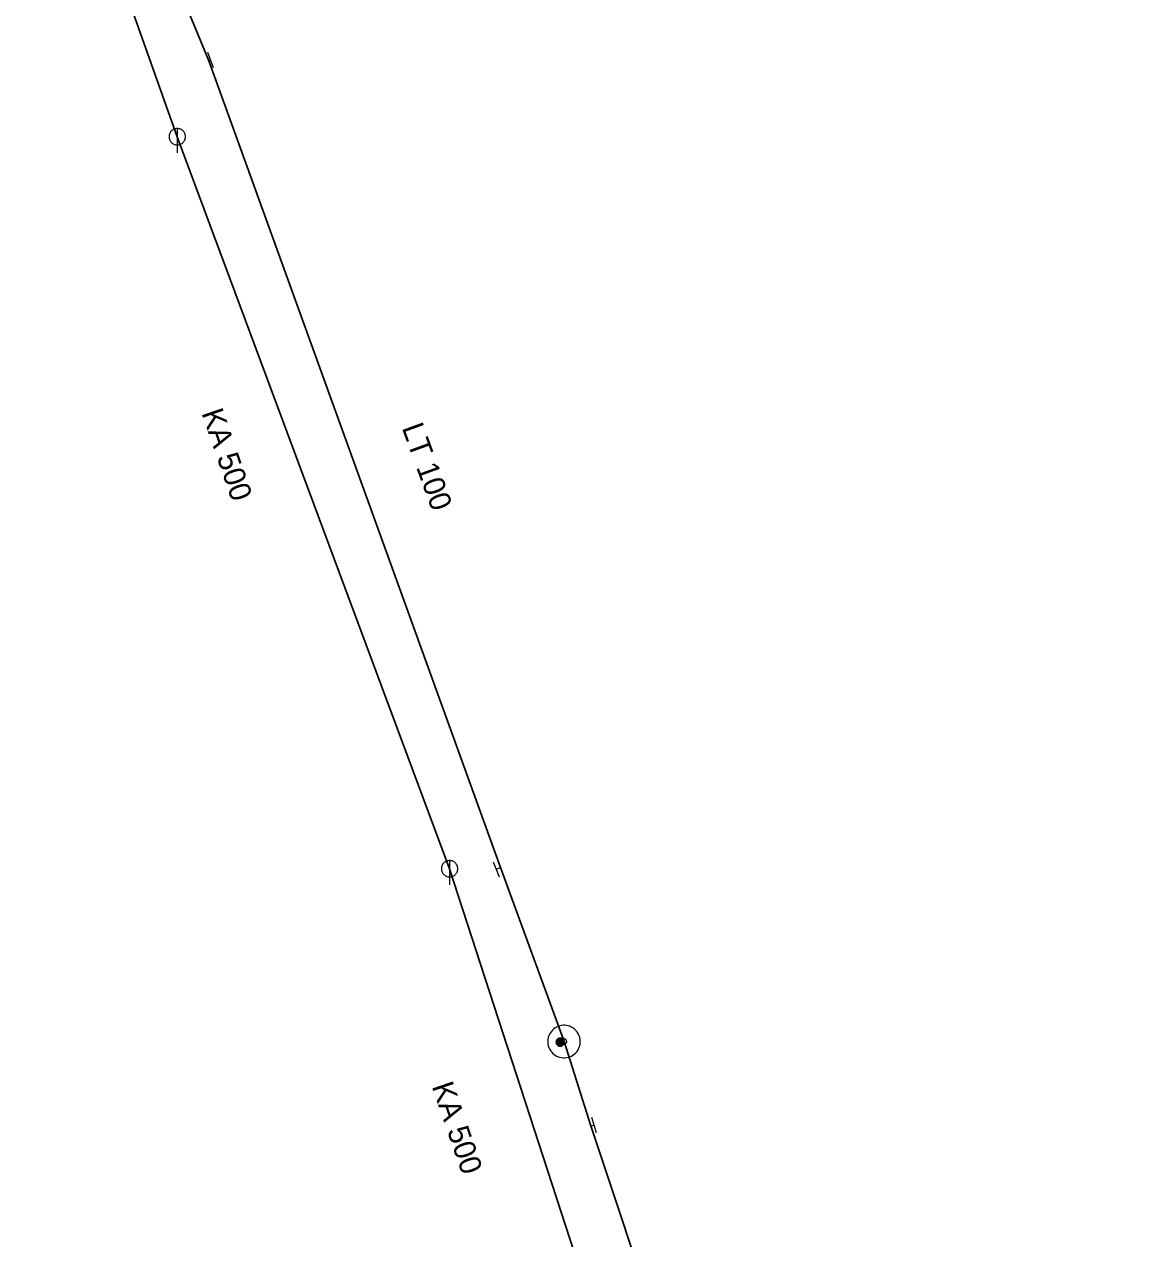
# Model space of a CAD drawing. Extents: x -687515 to -686506, y -974029 to -973461.
# Drawn here: x -687104.06 to -687069.66, y -973628.97 to -973591.65 of the extents above; entities that cross this region are included whole.
import ezdxf
from ezdxf.enums import TextEntityAlignment as Align

# ---------------------------------------------------------------- set-up
doc = ezdxf.new("R2010")
doc.units = 0
doc.header["$LTSCALE"] = 0.27
for name, color, linetype, lineweight in [('1', 7, 'Continuous', 13), ('14', 7, 'Continuous', 25), ('17', 7, 'Continuous', 25), ('22', 7, 'Continuous', 13), ('34', 7, 'Continuous', 13), ('47', 7, 'Continuous', 13), ('9', 7, 'Continuous', 13)]:
    doc.layers.add(name, color=color, linetype=linetype, lineweight=lineweight)

msp = doc.modelspace()

# ---------------------------------------------------------------- linework, layer by layer
at = {"layer": '14'}
for p, q in [((-687099.365, -973595.104), (-687104.065, -973581.877)), ((-687090.996, -973617.6), (-687099.365, -973595.104)), ((-687084.086, -973638.868), (-687090.996, -973617.6))]:
    msp.add_line(p, q, dxfattribs=at)
at = {"layer": '14', "lineweight": 13}
for p, q in [((-687098.39, -973592.77), (-687098.337, -973592.75)), ((-687089.426, -973617.563), (-687089.567, -973617.621)), ((-687087.478, -973622.912), (-687087.599, -973622.929)), ((-687086.649, -973625.5), (-687086.554, -973625.482))]:
    msp.add_line(p, q, dxfattribs=at)
at = {"layer": '17'}
for points in [[(-687087.478, -973622.912), (-687089.426, -973617.563), (-687098.39, -973592.77), (-687099.26, -973590.649), (-687102.57, -973581.78), (-687101.954, -973579.133)], [(-687069.662, -973676.57), (-687086.649, -973625.5), (-687087.478, -973622.912)]]:
    msp.add_lwpolyline(points, dxfattribs=at)
at = {"layer": '22'}
for p, q in [((-687099.364, -973594.852), (-687099.365, -973595.596)), ((-687090.995, -973617.348), (-687090.996, -973618.092))]:
    msp.add_line(p, q, dxfattribs=at)
for points in [[(-687099.113, -973595.104), (-687099.114, -973595.078), (-687099.118, -973595.052), (-687099.124, -973595.026), (-687099.134, -973595.002), (-687099.146, -973594.978), (-687099.16, -973594.956), (-687099.177, -973594.935), (-687099.195, -973594.917), (-687099.216, -973594.9), (-687099.238, -973594.886), (-687099.262, -973594.874), (-687099.286, -973594.864), (-687099.312, -973594.858), (-687099.338, -973594.854), (-687099.364, -973594.852), (-687099.39, -973594.853), (-687099.416, -973594.857), (-687099.442, -973594.863), (-687099.467, -973594.873), (-687099.49, -973594.885), (-687099.512, -973594.899), (-687099.533, -973594.916), (-687099.551, -973594.934), (-687099.568, -973594.955), (-687099.582, -973594.977), (-687099.594, -973595.001), (-687099.604, -973595.025), (-687099.611, -973595.051), (-687099.615, -973595.077), (-687099.617, -973595.103), (-687099.616, -973595.129), (-687099.612, -973595.155), (-687099.605, -973595.181), (-687099.595, -973595.206), (-687099.583, -973595.229), (-687099.569, -973595.251), (-687099.552, -973595.272), (-687099.534, -973595.29), (-687099.513, -973595.307), (-687099.491, -973595.321), (-687099.468, -973595.333), (-687099.443, -973595.343), (-687099.417, -973595.35), (-687099.391, -973595.354), (-687099.365, -973595.356), (-687099.339, -973595.355), (-687099.313, -973595.351), (-687099.287, -973595.344), (-687099.263, -973595.334), (-687099.239, -973595.322), (-687099.217, -973595.308), (-687099.196, -973595.291), (-687099.178, -973595.273), (-687099.161, -973595.252), (-687099.147, -973595.23), (-687099.135, -973595.207), (-687099.125, -973595.182), (-687099.119, -973595.156), (-687099.115, -973595.13)], [(-687090.744, -973617.6), (-687090.745, -973617.574), (-687090.749, -973617.548), (-687090.755, -973617.522), (-687090.765, -973617.498), (-687090.777, -973617.474), (-687090.791, -973617.452), (-687090.808, -973617.431), (-687090.826, -973617.413), (-687090.847, -973617.396), (-687090.869, -973617.382), (-687090.893, -973617.37), (-687090.917, -973617.36), (-687090.943, -973617.354), (-687090.969, -973617.35), (-687090.995, -973617.348), (-687091.021, -973617.349), (-687091.047, -973617.353), (-687091.073, -973617.359), (-687091.098, -973617.369), (-687091.121, -973617.381), (-687091.143, -973617.395), (-687091.164, -973617.412), (-687091.182, -973617.43), (-687091.199, -973617.451), (-687091.213, -973617.473), (-687091.225, -973617.497), (-687091.235, -973617.521), (-687091.242, -973617.547), (-687091.246, -973617.573), (-687091.248, -973617.599), (-687091.247, -973617.625), (-687091.243, -973617.651), (-687091.236, -973617.677), (-687091.226, -973617.702), (-687091.214, -973617.725), (-687091.2, -973617.747), (-687091.183, -973617.768), (-687091.165, -973617.786), (-687091.144, -973617.803), (-687091.122, -973617.817), (-687091.099, -973617.829), (-687091.074, -973617.839), (-687091.048, -973617.846), (-687091.022, -973617.85), (-687090.996, -973617.852), (-687090.97, -973617.851), (-687090.944, -973617.847), (-687090.918, -973617.84), (-687090.894, -973617.83), (-687090.87, -973617.818), (-687090.848, -973617.804), (-687090.827, -973617.787), (-687090.809, -973617.769), (-687090.792, -973617.748), (-687090.778, -973617.726), (-687090.766, -973617.703), (-687090.756, -973617.678), (-687090.75, -973617.652), (-687090.746, -973617.626)]]:
    msp.add_lwpolyline(points, close=True, dxfattribs=at)
at = {"layer": '34'}
for p, q in [((-687098.249, -973592.981), (-687098.424, -973592.518)), ((-687089.66, -973617.391), (-687089.473, -973617.85)), ((-687086.48, -973625.718), (-687086.627, -973625.245))]:
    msp.add_line(p, q, dxfattribs=at)
at = {"layer": '47'}
for points in [[(-687087.297, -973623.378), (-687087.249, -973623.356), (-687087.204, -973623.33), (-687087.162, -973623.299), (-687087.123, -973623.264), (-687087.088, -973623.225), (-687087.057, -973623.182), (-687087.032, -973623.137), (-687087.011, -973623.089), (-687086.995, -973623.04), (-687086.983, -973622.988), (-687086.978, -973622.936), (-687086.979, -973622.883), (-687086.984, -973622.832), (-687086.995, -973622.78), (-687087.011, -973622.731), (-687087.033, -973622.683), (-687087.059, -973622.638), (-687087.091, -973622.595), (-687087.125, -973622.557), (-687087.164, -973622.522), (-687087.207, -973622.491), (-687087.253, -973622.465), (-687087.3, -973622.444), (-687087.35, -973622.428), (-687087.401, -973622.417), (-687087.453, -973622.412), (-687087.506, -973622.412), (-687087.557, -973622.418), (-687087.609, -973622.429), (-687087.658, -973622.445), (-687087.706, -973622.467), (-687087.751, -973622.493), (-687087.794, -973622.524), (-687087.832, -973622.559), (-687087.867, -973622.598), (-687087.898, -973622.64), (-687087.924, -973622.686), (-687087.945, -973622.734), (-687087.961, -973622.784), (-687087.972, -973622.835), (-687087.977, -973622.887), (-687087.977, -973622.939), (-687087.971, -973622.991), (-687087.96, -973623.043), (-687087.944, -973623.092), (-687087.922, -973623.14), (-687087.896, -973623.185), (-687087.866, -973623.227), (-687087.83, -973623.266), (-687087.791, -973623.301), (-687087.749, -973623.332), (-687087.704, -973623.357), (-687087.656, -973623.378), (-687087.606, -973623.394), (-687087.554, -973623.406), (-687087.502, -973623.411), (-687087.45, -973623.41), (-687087.398, -973623.405), (-687087.346, -973623.394)], [(-687087.448, -973622.988), (-687087.439, -973622.985), (-687087.433, -973622.98), (-687087.426, -973622.975), (-687087.42, -973622.97), (-687087.414, -973622.963), (-687087.409, -973622.956), (-687087.404, -973622.949), (-687087.401, -973622.941), (-687087.399, -973622.932), (-687087.396, -973622.924), (-687087.396, -973622.915), (-687087.396, -973622.907), (-687087.397, -973622.898), (-687087.398, -973622.89), (-687087.401, -973622.882), (-687087.404, -973622.873), (-687087.409, -973622.867), (-687087.414, -973622.86), (-687087.419, -973622.854), (-687087.426, -973622.848), (-687087.433, -973622.843), (-687087.44, -973622.838), (-687087.448, -973622.835), (-687087.457, -973622.832), (-687087.465, -973622.83), (-687087.474, -973622.83), (-687087.482, -973622.83), (-687087.491, -973622.831), (-687087.499, -973622.832), (-687087.507, -973622.835), (-687087.516, -973622.838), (-687087.522, -973622.843), (-687087.529, -973622.848), (-687087.535, -973622.853), (-687087.541, -973622.86), (-687087.546, -973622.866), (-687087.551, -973622.874), (-687087.554, -973622.882), (-687087.557, -973622.891), (-687087.559, -973622.899), (-687087.559, -973622.908), (-687087.559, -973622.916), (-687087.558, -973622.925), (-687087.557, -973622.933), (-687087.554, -973622.941), (-687087.551, -973622.95), (-687087.546, -973622.956), (-687087.541, -973622.963), (-687087.536, -973622.969), (-687087.529, -973622.975), (-687087.523, -973622.98), (-687087.515, -973622.985), (-687087.507, -973622.988), (-687087.498, -973622.99), (-687087.49, -973622.993), (-687087.481, -973622.993), (-687087.473, -973622.993), (-687087.464, -973622.992), (-687087.456, -973622.991)]]:
    msp.add_lwpolyline(points, close=True, dxfattribs=at)
at = {"layer": '9'}
for points in [[(-687087.473, -973622.929), (-687087.474, -973622.916), (-687087.476, -973622.903), (-687087.479, -973622.89), (-687087.484, -973622.878), (-687087.49, -973622.866), (-687087.497, -973622.855), (-687087.505, -973622.845), (-687087.515, -973622.835), (-687087.525, -973622.827), (-687087.536, -973622.82), (-687087.548, -973622.814), (-687087.56, -973622.809), (-687087.573, -973622.806), (-687087.586, -973622.804), (-687087.599, -973622.803), (-687087.612, -973622.804), (-687087.625, -973622.806), (-687087.638, -973622.809), (-687087.65, -973622.814), (-687087.662, -973622.82), (-687087.673, -973622.827), (-687087.683, -973622.835), (-687087.693, -973622.845), (-687087.701, -973622.855), (-687087.708, -973622.866), (-687087.714, -973622.878), (-687087.719, -973622.89), (-687087.722, -973622.903), (-687087.724, -973622.916), (-687087.725, -973622.929), (-687087.724, -973622.942), (-687087.722, -973622.955), (-687087.719, -973622.968), (-687087.714, -973622.98), (-687087.708, -973622.992), (-687087.701, -973623.003), (-687087.693, -973623.013), (-687087.683, -973623.023), (-687087.673, -973623.031), (-687087.662, -973623.038), (-687087.65, -973623.044), (-687087.638, -973623.049), (-687087.625, -973623.052), (-687087.612, -973623.054), (-687087.599, -973623.055), (-687087.586, -973623.054), (-687087.573, -973623.052), (-687087.56, -973623.049), (-687087.548, -973623.044), (-687087.536, -973623.038), (-687087.525, -973623.031), (-687087.515, -973623.023), (-687087.505, -973623.013), (-687087.497, -973623.003), (-687087.49, -973622.992), (-687087.484, -973622.98), (-687087.479, -973622.968), (-687087.476, -973622.955), (-687087.474, -973622.942)], [(-687087.493, -973622.929), (-687087.493, -973622.918), (-687087.495, -973622.907), (-687087.498, -973622.896), (-687087.502, -973622.886), (-687087.507, -973622.876), (-687087.513, -973622.867), (-687087.52, -973622.858), (-687087.528, -973622.85), (-687087.537, -973622.843), (-687087.546, -973622.837), (-687087.556, -973622.832), (-687087.566, -973622.828), (-687087.577, -973622.825), (-687087.588, -973622.823), (-687087.599, -973622.823), (-687087.61, -973622.823), (-687087.621, -973622.825), (-687087.632, -973622.828), (-687087.642, -973622.832), (-687087.652, -973622.837), (-687087.661, -973622.843), (-687087.67, -973622.85), (-687087.678, -973622.858), (-687087.685, -973622.867), (-687087.691, -973622.876), (-687087.696, -973622.886), (-687087.7, -973622.896), (-687087.703, -973622.907), (-687087.705, -973622.918), (-687087.705, -973622.929), (-687087.705, -973622.94), (-687087.703, -973622.951), (-687087.7, -973622.962), (-687087.696, -973622.972), (-687087.691, -973622.982), (-687087.685, -973622.991), (-687087.678, -973623), (-687087.67, -973623.008), (-687087.661, -973623.015), (-687087.652, -973623.021), (-687087.642, -973623.026), (-687087.632, -973623.03), (-687087.621, -973623.033), (-687087.61, -973623.035), (-687087.599, -973623.035), (-687087.588, -973623.035), (-687087.577, -973623.033), (-687087.566, -973623.03), (-687087.556, -973623.026), (-687087.546, -973623.021), (-687087.537, -973623.015), (-687087.528, -973623.008), (-687087.52, -973623), (-687087.513, -973622.991), (-687087.507, -973622.982), (-687087.502, -973622.972), (-687087.498, -973622.962), (-687087.495, -973622.951), (-687087.493, -973622.94)], [(-687087.512, -973622.929), (-687087.513, -973622.92), (-687087.514, -973622.911), (-687087.517, -973622.902), (-687087.52, -973622.894), (-687087.524, -973622.886), (-687087.529, -973622.878), (-687087.535, -973622.871), (-687087.541, -973622.865), (-687087.548, -973622.859), (-687087.556, -973622.854), (-687087.564, -973622.85), (-687087.572, -973622.847), (-687087.581, -973622.844), (-687087.59, -973622.843), (-687087.599, -973622.842), (-687087.608, -973622.843), (-687087.617, -973622.844), (-687087.626, -973622.847), (-687087.634, -973622.85), (-687087.642, -973622.854), (-687087.65, -973622.859), (-687087.657, -973622.865), (-687087.663, -973622.871), (-687087.669, -973622.878), (-687087.674, -973622.886), (-687087.678, -973622.894), (-687087.681, -973622.902), (-687087.684, -973622.911), (-687087.685, -973622.92), (-687087.686, -973622.929), (-687087.685, -973622.938), (-687087.684, -973622.947), (-687087.681, -973622.956), (-687087.678, -973622.964), (-687087.674, -973622.972), (-687087.669, -973622.98), (-687087.663, -973622.987), (-687087.657, -973622.993), (-687087.65, -973622.999), (-687087.642, -973623.004), (-687087.634, -973623.008), (-687087.626, -973623.011), (-687087.617, -973623.014), (-687087.608, -973623.015), (-687087.599, -973623.016), (-687087.59, -973623.015), (-687087.581, -973623.014), (-687087.572, -973623.011), (-687087.564, -973623.008), (-687087.556, -973623.004), (-687087.548, -973622.999), (-687087.541, -973622.993), (-687087.535, -973622.987), (-687087.529, -973622.98), (-687087.524, -973622.972), (-687087.52, -973622.964), (-687087.517, -973622.956), (-687087.514, -973622.947), (-687087.513, -973622.938)], [(-687087.532, -973622.929), (-687087.532, -973622.922), (-687087.534, -973622.915), (-687087.535, -973622.908), (-687087.538, -973622.902), (-687087.541, -973622.896), (-687087.545, -973622.89), (-687087.549, -973622.884), (-687087.554, -973622.879), (-687087.56, -973622.875), (-687087.566, -973622.871), (-687087.572, -973622.868), (-687087.578, -973622.865), (-687087.585, -973622.864), (-687087.592, -973622.862), (-687087.599, -973622.862), (-687087.606, -973622.862), (-687087.613, -973622.864), (-687087.62, -973622.865), (-687087.626, -973622.868), (-687087.633, -973622.871), (-687087.638, -973622.875), (-687087.644, -973622.879), (-687087.649, -973622.884), (-687087.653, -973622.89), (-687087.657, -973622.896), (-687087.66, -973622.902), (-687087.663, -973622.908), (-687087.665, -973622.915), (-687087.666, -973622.922), (-687087.666, -973622.929), (-687087.666, -973622.936), (-687087.665, -973622.943), (-687087.663, -973622.95), (-687087.66, -973622.956), (-687087.657, -973622.963), (-687087.653, -973622.968), (-687087.649, -973622.974), (-687087.644, -973622.979), (-687087.638, -973622.983), (-687087.633, -973622.987), (-687087.626, -973622.99), (-687087.62, -973622.993), (-687087.613, -973622.995), (-687087.606, -973622.996), (-687087.599, -973622.996), (-687087.592, -973622.996), (-687087.585, -973622.995), (-687087.578, -973622.993), (-687087.572, -973622.99), (-687087.566, -973622.987), (-687087.56, -973622.983), (-687087.554, -973622.979), (-687087.549, -973622.974), (-687087.545, -973622.968), (-687087.541, -973622.963), (-687087.538, -973622.956), (-687087.535, -973622.95), (-687087.534, -973622.943), (-687087.532, -973622.936)], [(-687087.552, -973622.929), (-687087.552, -973622.924), (-687087.553, -973622.919), (-687087.554, -973622.914), (-687087.556, -973622.91), (-687087.558, -973622.905), (-687087.561, -973622.901), (-687087.564, -973622.898), (-687087.568, -973622.894), (-687087.571, -973622.891), (-687087.575, -973622.888), (-687087.58, -973622.886), (-687087.584, -973622.884), (-687087.589, -973622.883), (-687087.594, -973622.882), (-687087.599, -973622.882), (-687087.604, -973622.882), (-687087.609, -973622.883), (-687087.614, -973622.884), (-687087.618, -973622.886), (-687087.623, -973622.888), (-687087.627, -973622.891), (-687087.631, -973622.894), (-687087.634, -973622.898), (-687087.637, -973622.901), (-687087.64, -973622.905), (-687087.642, -973622.91), (-687087.644, -973622.914), (-687087.645, -973622.919), (-687087.646, -973622.924), (-687087.646, -973622.929), (-687087.646, -973622.934), (-687087.645, -973622.939), (-687087.644, -973622.944), (-687087.642, -973622.948), (-687087.64, -973622.953), (-687087.637, -973622.957), (-687087.634, -973622.961), (-687087.631, -973622.964), (-687087.627, -973622.967), (-687087.623, -973622.97), (-687087.618, -973622.972), (-687087.614, -973622.974), (-687087.609, -973622.975), (-687087.604, -973622.976), (-687087.599, -973622.976), (-687087.594, -973622.976), (-687087.589, -973622.975), (-687087.584, -973622.974), (-687087.58, -973622.972), (-687087.575, -973622.97), (-687087.571, -973622.967), (-687087.568, -973622.964), (-687087.564, -973622.961), (-687087.561, -973622.957), (-687087.558, -973622.953), (-687087.556, -973622.948), (-687087.554, -973622.944), (-687087.553, -973622.939), (-687087.552, -973622.934)], [(-687087.572, -973622.929), (-687087.572, -973622.926), (-687087.572, -973622.923), (-687087.573, -973622.921), (-687087.574, -973622.918), (-687087.575, -973622.915), (-687087.577, -973622.913), (-687087.579, -973622.911), (-687087.581, -973622.909), (-687087.583, -973622.907), (-687087.585, -973622.905), (-687087.588, -973622.904), (-687087.591, -973622.903), (-687087.593, -973622.902), (-687087.596, -973622.902), (-687087.599, -973622.902), (-687087.602, -973622.902), (-687087.605, -973622.902), (-687087.608, -973622.903), (-687087.61, -973622.904), (-687087.613, -973622.905), (-687087.615, -973622.907), (-687087.618, -973622.909), (-687087.62, -973622.911), (-687087.621, -973622.913), (-687087.623, -973622.915), (-687087.624, -973622.918), (-687087.625, -973622.921), (-687087.626, -973622.923), (-687087.626, -973622.926), (-687087.627, -973622.929), (-687087.626, -973622.932), (-687087.626, -973622.935), (-687087.625, -973622.938), (-687087.624, -973622.94), (-687087.623, -973622.943), (-687087.621, -973622.945), (-687087.62, -973622.948), (-687087.618, -973622.95), (-687087.615, -973622.951), (-687087.613, -973622.953), (-687087.61, -973622.954), (-687087.608, -973622.955), (-687087.605, -973622.956), (-687087.602, -973622.956), (-687087.599, -973622.957), (-687087.596, -973622.956), (-687087.593, -973622.956), (-687087.591, -973622.955), (-687087.588, -973622.954), (-687087.585, -973622.953), (-687087.583, -973622.951), (-687087.581, -973622.95), (-687087.579, -973622.948), (-687087.577, -973622.945), (-687087.575, -973622.943), (-687087.574, -973622.94), (-687087.573, -973622.938), (-687087.572, -973622.935), (-687087.572, -973622.932)], [(-687087.591, -973622.929), (-687087.591, -973622.928), (-687087.591, -973622.927), (-687087.592, -973622.927), (-687087.592, -973622.926), (-687087.592, -973622.925), (-687087.593, -973622.924), (-687087.593, -973622.924), (-687087.594, -973622.923), (-687087.594, -973622.923), (-687087.595, -973622.922), (-687087.596, -973622.922), (-687087.597, -973622.922), (-687087.597, -973622.921), (-687087.598, -973622.921), (-687087.599, -973622.921), (-687087.6, -973622.921), (-687087.601, -973622.921), (-687087.601, -973622.922), (-687087.602, -973622.922), (-687087.603, -973622.922), (-687087.604, -973622.923), (-687087.604, -973622.923), (-687087.605, -973622.924), (-687087.605, -973622.924), (-687087.606, -973622.925), (-687087.606, -973622.926), (-687087.607, -973622.927), (-687087.607, -973622.927), (-687087.607, -973622.928), (-687087.607, -973622.929), (-687087.607, -973622.93), (-687087.607, -973622.931), (-687087.607, -973622.931), (-687087.606, -973622.932), (-687087.606, -973622.933), (-687087.605, -973622.934), (-687087.605, -973622.934), (-687087.604, -973622.935), (-687087.604, -973622.935), (-687087.603, -973622.936), (-687087.602, -973622.936), (-687087.601, -973622.937), (-687087.601, -973622.937), (-687087.6, -973622.937), (-687087.599, -973622.937), (-687087.598, -973622.937), (-687087.597, -973622.937), (-687087.597, -973622.937), (-687087.596, -973622.936), (-687087.595, -973622.936), (-687087.594, -973622.935), (-687087.594, -973622.935), (-687087.593, -973622.934), (-687087.593, -973622.934), (-687087.592, -973622.933), (-687087.592, -973622.932), (-687087.592, -973622.931), (-687087.591, -973622.931), (-687087.591, -973622.93)]]:
    msp.add_lwpolyline(points, close=True, dxfattribs=at)

# ---------------------------------------------------------------- texts
at = {"layer": '1'}
for s, rotation, p in [('KA 500', 289, (-687098.147, -973604.974)), ('LT 100', 290, (-687091.994, -973605.349)), ('KA 500', 289, (-687091.071, -973625.667))]:
    msp.add_text(s, height=0.6667, rotation=rotation, dxfattribs=at).set_placement(p, align=Align.CENTER)

doc.saveas('drawing.dxf')
